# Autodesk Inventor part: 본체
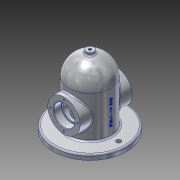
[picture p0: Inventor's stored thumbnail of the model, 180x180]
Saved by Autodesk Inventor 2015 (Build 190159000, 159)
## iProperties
Created: 2019-11
Part Number: 본체
Material: 알루미늄 6061
Document SubType Name: Modeling
Designer: Lineart
Density: 2.7 g/cm^3
Appearance: 알루미늄 - 평지
Mass: 1106.12 g
Surface Area: 883.263 cm^2
Volume: 409.676 cm^3
Author: Lineart
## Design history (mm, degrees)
sketch "스케치1"
  geometry: L1 (0, 0)-(-70, 0); L2 (-70, 0)-(-70, 10); L3 (-70, 10)-(-40, 10); L4 (-40, 10)-(-40, 90); L5 (0, 0)-(0, 130); A1 r 40 centre (0, 90) between (0, 130) and (-40, 90)
  constraints: 10 end point, 3 perpendicular, 2 point on circle, 1 centre point, 1 horizontal, 1 point on line, 1 vertical, 1 vertical alignment
  dimensions: "d0" = 70 distance of L1.start L1.end; "d1" = 10 distance of L1.end L2.end; "d2" = 40 distance between parallel lines of L5 L4; "d3" = 40 radius of A1; "d4" = 130 distance of L1.start L5.end
revolve "회전1" sketch "스케치1" stored, may be unused: angle "d5" = 90 deg
sketch "스케치2"
  geometry: C1 r 31 at (0, 50); A1 r 40 centre (0, 90) between (40, 90) and (-40, 90) reference; 1 further point
  constraints: 1 centre point, 1 vertical alignment
  dimensions: "d6" = 62 diameter of C1; "d7" = 50 distance of point (0, 0) C1.centre
extrude "돌출1" join sketch "스케치2" stored distance "d8" = 100; taper "d9" = 0 deg
sketch "스케치4"
  geometry: L1 (0, 0)-(-30, 0); L2 (70, 0)-(-70, 0) reference; L3 (-30, 0)-(-30, 90); L4 (40, 90)-(-40, 90) reference; L5 (0, 0)-(0, 120); A1 r 40 centre (0, 90) between (40, 90) and (-40, 90) reference; A2 r 30 centre (0, 90) between (0, 120) and (-30, 90)
  constraints: 6 end point, 2 point on circle, 2 point on line, 1 centre point, 1 coincident, 1 perpendicular, 1 vertical
  dimensions: "d13" = 30 distance of L1.start L1.end
revolve "회전2" sketch "스케치4" stored, may be unused: angle "d14" = 90 deg
hole "구멍1" diameter "d17" = 33; stored, may be unused: countersink angle "d21" = 90 deg, drill point angle "d23" = 118 deg; dims "d15" = 10, "d16" = 10, "d18" = 6, "d19" = 40, "d20" = 15, "d22" = 8
sketch "스케치5"
  geometry: C1 r 16.5 at (0, 0) reference; C2 r 20 at (0, 0); 1 further point
  constraints: 1 centre point, 1 coincident
  dimensions: "d24" = 40 diameter of C2
extrude "돌출2" cut sketch "스케치5" distance "d25" = 15; taper "d26" = 0 deg
node "작업 평면1"
sketch "스케치6"
  geometry: C1 r 7.5 at (0, 0); 1 further point
  constraints: 1 centre point, 1 coincident
  dimensions: "d28" = 15 diameter of C1
extrude "돌출3" join sketch "스케치6" stored distance "d29" = 15; taper "d30" = 0 deg
hole "구멍2" diameter "d33" = 5.188; stored, may be unused: countersink angle "d37" = 90 deg, drill point angle "d39" = 118 deg; dims "d31" = 10, "d32" = 10, "d34" = 12, "d35" = 40, "d36" = 15, "d38" = 16
sketch "스케치7"
  geometry: L1 (0, 0)-(0, -26); L2 (0, 0)-(26, 0); L3 (0, 0)-(0, 26); L4 (0, 0)-(-26, 0); C1 r 16.5 at (0, 0) reference; 1 further point
  constraints: 8 end point, 2 coincident, 1 vertical, 11 other
  dimensions: "d40" = 26 distance of L1.start L1.end; "d43" = 360 deg dimension on L1.start L1.end (derived)
hole "구멍3" sketch "스케치7" at (-26, 0), (0, 26), (0, -26), (26, 0) diameter "d45" = 3.242; stored, may be unused: countersink angle "d49" = 90 deg, drill point angle "d51" = 118 deg; dims "d46" = 8, "d47" = 40, "d48" = 15, "d50" = 10
fillet "모깎기1" dims "d52" = 3
sketch "스케치8"
  geometry: L1 (0, 0)-(-55, 0); L2 (0, 0)-(55, 0); C1 r 4.5 at (-55, 0); C2 r 4.5 at (55, 0)
  constraints: 4 end point, 2 centre point, 2 coincident, 2 horizontal
  dimensions: "d53" = 55 distance of L1.start L1.end; "d54" = 9 diameter of C1; "d55" = 55 distance of L1.start L2.end; "d56" = 9 diameter of C2
extrude "돌출4" cut sketch "스케치8" stored distance "d57" = 15; taper "d58" = 0 deg
node "작업 평면2"
sketch "스케치9"
  geometry: L1 (70, 0)-(-70, 0) reference; 3 further points
  constraints: 1 midpoint, 1 vertical alignment, 1 other
  dimensions: "d60" = 50 distance from line of L1 point (0, 50)
feature "엠보싱1" sketch "스케치9" dims "d0" = 70, "d1" = 10, "d2" = 40, "d3" = 40, "d4" = 130, "d61" = 0.5, "d62" = 0
fillet "모깎기2" dims "d63" = 0.3
chamfer "모따기1" distance "d64" = 1; stored, may be unused: second distance "d65" = 2, angle "d66" = 45 deg
node "솔리드1"
mirror "대칭1"
other parameters: "d27" = -135
